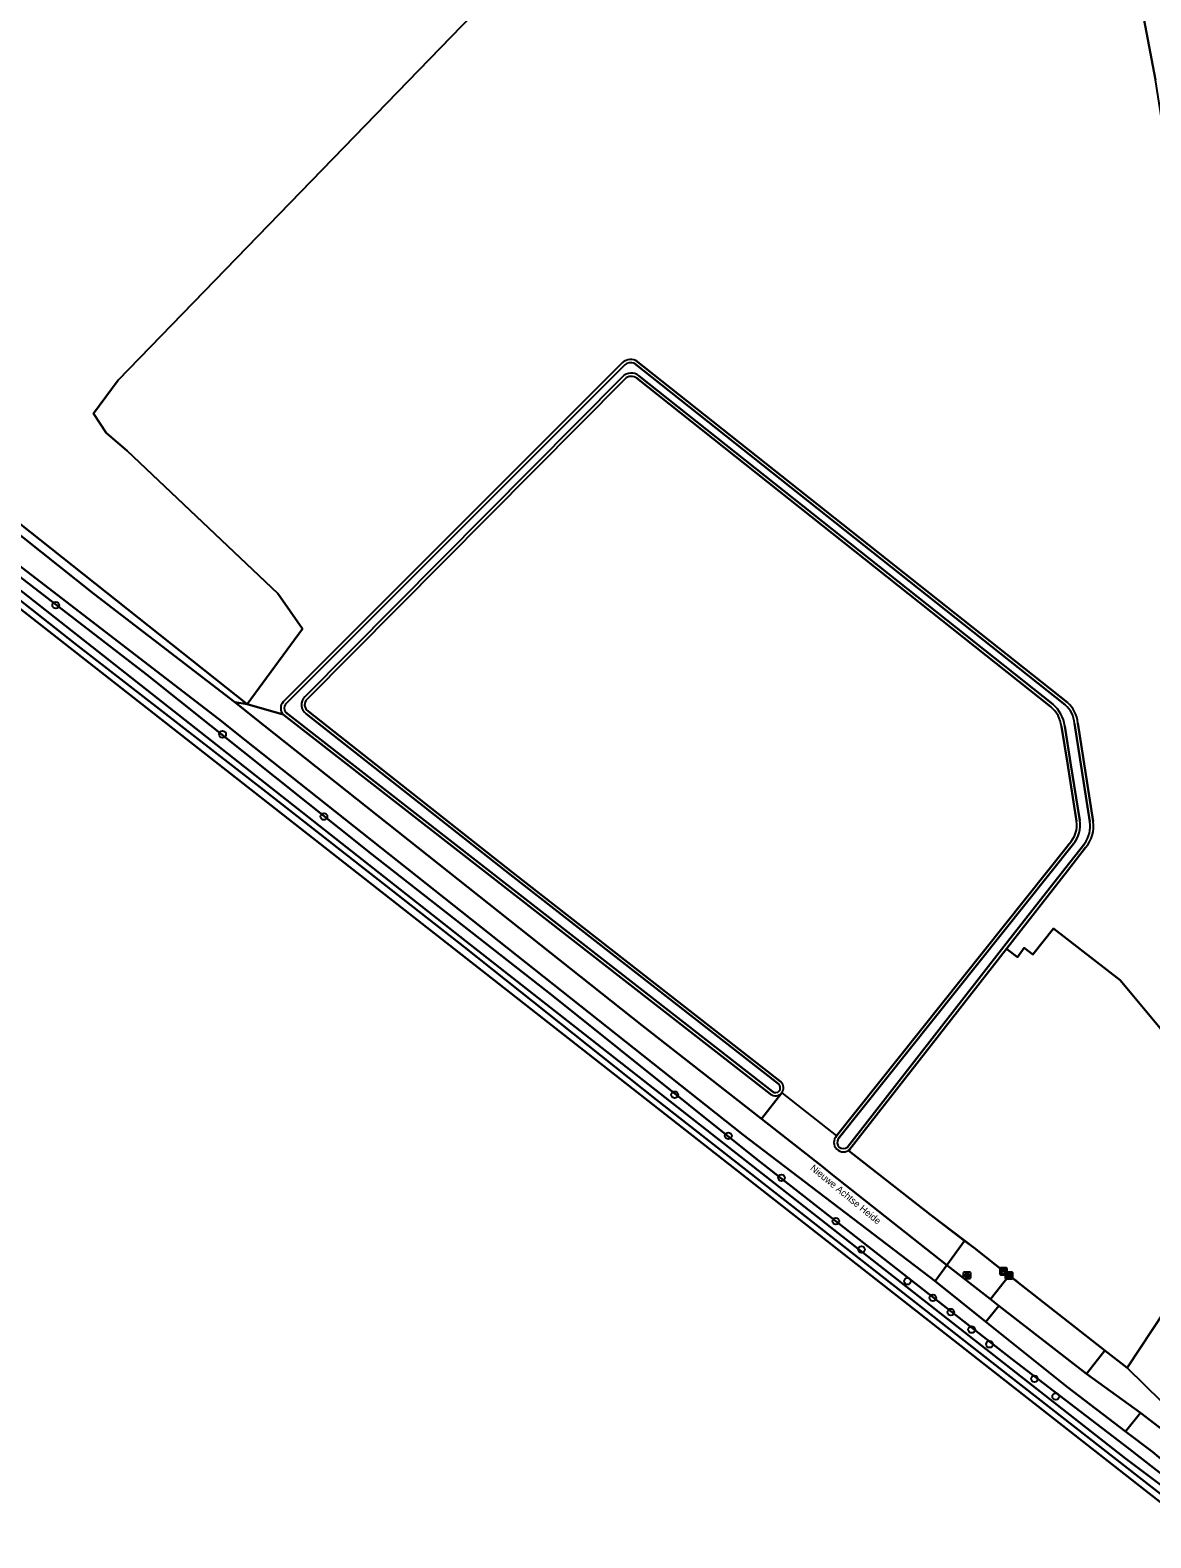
# Model space of a CAD drawing. Extents: x 155209 to 156748, y 385356 to 388487.
# Drawn here: x 155848.9 to 156012.2, y 387555.6 to 387775.3 of the extents above; entities that cross this region are included whole.
import ezdxf

# ---------------------------------------------------------------- set-up
doc = ezdxf.new("R2010")
doc.units = 0
for name, color, linetype in [('IMGEO_Boom', 7, 'Continuous'), ('IMGEO_Bouwland', 7, 'Continuous'), ('IMGEO_Duiker', 7, 'Continuous'), ('IMGEO_Erf', 7, 'Continuous'), ('IMGEO_Grasland_overig', 7, 'Continuous'), ('IMGEO_Groenvoorziening', 7, 'Continuous'), ('IMGEO_Kast', 7, 'Continuous'), ('IMGEO_Loofbos', 7, 'Continuous'), ('IMGEO_Muur', 7, 'Continuous'), ('IMGEO_Oever', 7, 'Continuous'), ('IMGEO_Openbare_ruimte_label', 7, 'Continuous'), ('IMGEO_Rijbaan_lokaal_gesloten', 7, 'Continuous'), ('IMGEO_Rijbaan_lokaal_onverhard', 7, 'Continuous'), ('IMGEO_Rijbaan_lokaal_open', 7, 'Continuous'), ('IMGEO_Rioolput', 7, 'Continuous'), ('IMGEO_Sloot', 7, 'Continuous'), ('IMGEO_Voetpad_open', 7, 'Continuous'), ('IMGEO_Waterloop', 7, 'Continuous')]:
    doc.layers.add(name, color=color, linetype=linetype)

msp = doc.modelspace()

# ---------------------------------------------------------------- linework, layer by layer
at = {"layer": 'IMGEO_Boom'}
for centre in [(155852.58, 387691.54), (155876.9, 387672.71), (155891.66, 387660.72), (155942.77, 387620.19), (155950.59, 387614.19), (155958.34, 387608.09), (155966.26, 387601.76), (155969.99, 387597.64), (155976.7, 387593.01), (155980.4, 387590.59), (155983.01, 387588.52), (155986.05, 387585.96), (155988.65, 387583.82), (155995.21, 387578.79), (155998.3, 387576.22)]:
    msp.add_circle(centre, 0.489, dxfattribs=at)
at = {"layer": 'IMGEO_Bouwland'}
for points in [[(155754.24, 387777.78), (155752.39, 387767.82), (155752.83, 387767.55), (155760.37, 387762.65), (155760.73, 387766.41), (155762.05, 387769.58), (155805.98, 387736.24), (155880.46, 387677.11), (155888.52, 387688.09), (155884.95, 387693.25), (155862.99, 387714.02), (155859.95, 387716.66), (155858.1, 387719.44), (155861.67, 387724.34), (155938.4, 387803.45)], [(156020.19, 387555.62), (156015.97, 387558.92), (156015.9, 387558.97), (155781.09, 387742.94), (155776.56, 387746.49), (155759.31, 387760.01), (155760.37, 387762.65), (155752.83, 387767.55), (155752.39, 387767.82), (155752.06, 387766.1), (155750.62, 387758.37), (155749.73, 387755.64), (155749.25, 387753.94), (155746.67, 387748.61), (155744.31, 387742.42), (155741.32, 387737.37), (155735.98, 387729.41), (155729.29, 387720.91), (155724.45, 387715.25), (155719.03, 387709.53), (155710.76, 387701.68), (155707.05, 387698.08), (155703.22, 387694.35), (155700.2, 387690.91)]]:
    msp.add_lwpolyline(points, dxfattribs=at)
at = {"layer": 'IMGEO_Duiker'}
msp.add_lwpolyline([(155958.37, 387620.45), (155966.36, 387614.2)], dxfattribs=at)
at = {"layer": 'IMGEO_Erf'}
msp.add_lwpolyline([(156013.5, 387629.9), (156007.67, 387636.87), (155998, 387644.4), (155994.98, 387640.64), (155993.71, 387641.58), (155992.72, 387640.24), (155991.14, 387641.47), (155968.32, 387612.24), (155968.13, 387612), (155980.01, 387602.73), (155985.03, 387598.91), (155986.4, 387597.87), (155989.48, 387595.46), (155991.51, 387593.86), (156005.46, 387582.93), (156008.69, 387580.4), (156023.21, 387602.29), (156025.53, 387607.15), (156026.18, 387610.83), (156025.05, 387613.71), (156022.6, 387616.69)], close=True, dxfattribs=at)
at = {"layer": 'IMGEO_Grasland_overig'}
for points in [[(156010.63, 387779.89), (156012.82, 387768.11)], [(155935.5, 387724.48), (155889.21, 387677.82)], [(155997.6, 387676.73), (155937.28, 387724.59)], [(155889.36, 387676.09), (155919.07, 387652.63), (155958.26, 387622.07)], [(156000, 387668.49), (155999.14, 387673.85)], [(156001.35, 387660.08), (156000, 387668.49)], [(155966.36, 387614.2), (156000, 387656.42), (156000.26, 387656.74)], [(155958.37, 387620.45), (155955.41, 387616.68), (155964.39, 387609.63), (155965.55, 387608.69), (155982.42, 387595.34), (155985.03, 387598.91), (155980.01, 387602.73), (155968.13, 387612), (155968.32, 387612.24)], [(156016.26, 387573.02), (156008.69, 387580.4), (156005.46, 387582.93), (156002.78, 387579.5), (156010.68, 387573.81), (156020.3, 387566.41)]]:
    msp.add_lwpolyline(points, dxfattribs=at)
msp.add_lwpolyline([(155805.98, 387736.24), (155762.05, 387769.58), (155760.73, 387766.41), (155760.37, 387762.65), (155761.75, 387762.78), (155763.39, 387767.02), (155776.38, 387757.04), (155816.85, 387726), (155858.15, 387693.18), (155878.67, 387677.4), (155880.46, 387677.11)], close=True, dxfattribs=at)
for centre, radius, start, end in [((155936.46, 387723.49), 1.38, 53.2962, 133.6598), ((155889.95, 387677.01), 1.1, 132.8115, 237.254), ((155994.61, 387673.27), 4.57, 7.3643, 49.1467), ((155997.41, 387659.52), 3.98, 315.771, 8.0723), ((155957.44, 387621.2), 1.19, 320.9755, 46.7373), ((155967.37, 387613.25), 1.39, 136.9935, 312.9481)]:
    msp.add_arc(centre, radius, start, end, dxfattribs=at)
at = {"layer": 'IMGEO_Groenvoorziening'}
for points in [[(155952.77, 387614.37), (155880.15, 387671.9), (155876.29, 387674.98), (155795.66, 387736.94), (155783.72, 387746.22), (155779.18, 387749.74), (155776.56, 387746.49), (155781.09, 387742.94), (155780.81, 387743.63), (155781.49, 387744.6), (155782.63, 387745.58), (155783.17, 387745.53), (155790.21, 387739.91), (155844.98, 387697.49), (155865.76, 387681.47), (155898.69, 387655.19), (155925.06, 387634.57), (155954.59, 387610.92), (155991.79, 387581.76), (156009, 387568.58), (156018.08, 387561.51)], [(156020.96, 387560.91), (156017.92, 387563.49), (156012.41, 387568.14), (156008.49, 387571.12), (156000, 387577.57), (155988.1, 387587.08), (155980.71, 387593), (155952.77, 387614.37)]]:
    msp.add_lwpolyline(points, dxfattribs=at)
at = {"layer": 'IMGEO_Kast'}
for p, q in [((155990.2, 387594.03), (155990.2, 387594.88)), ((155990.2, 387594.88), (155990.2, 387594.03)), ((155990.27, 387594.96), (155991.11, 387594.96)), ((155991.11, 387594.96), (155990.27, 387594.96)), ((155991, 387593.41), (155991, 387594.25)), ((155991, 387594.25), (155991, 387593.41)), ((155991.07, 387594.34), (155991.91, 387594.34)), ((155991.91, 387594.34), (155991.07, 387594.34)), ((155991.2, 387594.89), (155991.2, 387594.04)), ((155991.2, 387594.04), (155991.2, 387594.89)), ((155992, 387594.26), (155992, 387593.42)), ((155992, 387593.42), (155992, 387594.26)), ((155991.12, 387593.96), (155990.28, 387593.96)), ((155990.28, 387593.96), (155991.12, 387593.96)), ((155991.92, 387593.34), (155991.08, 387593.34)), ((155991.08, 387593.34), (155991.92, 387593.34))]:
    msp.add_line(p, q, dxfattribs=at)
for points in [[(155990.39, 387594.75), (155990.99, 387594.75), (155990.99, 387594.66), (155990.39, 387594.66), (155990.39, 387594.75)], [(155990.39, 387594.58), (155990.99, 387594.58), (155990.99, 387594.09), (155990.39, 387594.09), (155990.39, 387594.58)], [(155991.19, 387594.13), (155991.79, 387594.13), (155991.79, 387594.04), (155991.19, 387594.04), (155991.19, 387594.13)], [(155991.19, 387593.95), (155991.79, 387593.95), (155991.79, 387593.47), (155991.19, 387593.47), (155991.19, 387593.95)]]:
    msp.add_lwpolyline(points, dxfattribs=at)
for centre in [(155990.48, 387594.42), (155991.27, 387593.8)]:
    msp.add_circle(centre, 0.0377, dxfattribs=at)
for centre, start, end in [((155990.28, 387594.88), 92.4484, 184.2845), ((155990.28, 387594.88), 92.4484, 184.2845), ((155991.07, 387594.26), 92.4484, 184.2845), ((155991.07, 387594.26), 92.4484, 184.2845), ((155991.12, 387594.88), 2.4484, 94.2845), ((155991.12, 387594.88), 2.4484, 94.2845), ((155991.92, 387594.26), 2.4484, 94.2845), ((155991.92, 387594.26), 2.4484, 94.2845), ((155990.28, 387594.04), 182.4484, 274.2845), ((155990.28, 387594.04), 182.4484, 274.2845), ((155991.07, 387593.42), 182.4484, 274.2845), ((155991.07, 387593.42), 182.4484, 274.2845), ((155991.12, 387594.04), 272.4484, 4.2845), ((155991.12, 387594.04), 272.4484, 4.2845), ((155991.92, 387593.42), 272.4484, 4.2845), ((155991.92, 387593.42), 272.4484, 4.2845)]:
    msp.add_arc(centre, 0.0779, start, end, dxfattribs=at)
at = {"layer": 'IMGEO_Loofbos'}
for points in [[(156014.25, 387759.08), (156012.82, 387768.11), (156010.63, 387779.89), (156004.88, 387808.19), (156001.83, 387817.98), (156000.72, 387825.19), (156000.05, 387831.89), (155999.01, 387836.95), (155996.61, 387838.37), (155989.33, 387835.59), (155950.04, 387812.44), (155938.4, 387803.45), (155861.67, 387724.34), (155858.1, 387719.44), (155859.95, 387716.66), (155862.99, 387714.02), (155884.95, 387693.25), (155888.52, 387688.09), (155880.46, 387677.11), (155885.7, 387675.61)], [(155885.7, 387677.44), (155934.98, 387726.71)], [(155937.1, 387727.2), (156000, 387677.37)], [(155885.7, 387675.61), (155880.46, 387677.11), (155878.67, 387677.4), (155883, 387673.97), (155938.06, 387630.28), (155955.41, 387616.68), (155958.37, 387620.45)], [(155956.73, 387620.29), (155885.7, 387675.61)], [(156001.53, 387674.36), (156003.74, 387660.01)], [(156002.65, 387656.21), (156000, 387652.82), (155991.14, 387641.47), (155992.72, 387640.24), (155993.71, 387641.58), (155994.98, 387640.64), (155998, 387644.4), (156007.67, 387636.87), (156013.5, 387629.9)], [(156023.21, 387602.29), (156008.69, 387580.4), (156016.26, 387573.02)]]:
    msp.add_lwpolyline(points, dxfattribs=at)
for centre, radius, start, end in [((155936.39, 387725.41), 1.92, 68.3536, 137.4506), ((155886.8, 387676.52), 1.43, 140.1849, 219.8151), ((155996.96, 387673.92), 4.6, 5.4947, 48.5021), ((155999.24, 387659.25), 4.57, 318.292, 9.5745), ((155957.47, 387621.22), 1.18, 231.855, 319.6702)]:
    msp.add_arc(centre, radius, start, end, dxfattribs=at)
at = {"layer": 'IMGEO_Muur'}
for points in [[(155992.72, 387640.24), (155993.71, 387641.58), (155994.98, 387640.64), (155998, 387644.4), (156007.67, 387636.87), (156013.5, 387629.9), (156022.6, 387616.69), (156025.05, 387613.71), (156026.18, 387610.83), (156025.53, 387607.15), (156023.21, 387602.29), (156008.69, 387580.4)], [(155980.01, 387602.73), (155986.4, 387597.87)], [(155989.48, 387595.46), (155992.71, 387592.93)], [(156008.69, 387580.4), (155994.6, 387591.45)]]:
    msp.add_lwpolyline(points, dxfattribs=at)
at = {"layer": 'IMGEO_Oever'}
for points in [[(156018.08, 387561.51), (156009, 387568.58), (155991.79, 387581.76), (155954.59, 387610.92), (155925.06, 387634.57), (155898.69, 387655.19), (155865.76, 387681.47), (155844.98, 387697.49), (155790.21, 387739.91), (155783.17, 387745.53), (155782.63, 387745.58), (155781.49, 387744.6), (155780.81, 387743.63), (155781.09, 387742.94)], [(155781.09, 387742.94), (156015.9, 387558.97), (156015.97, 387558.92)], [(155934.98, 387726.71), (155885.7, 387677.44)], [(155886.06, 387677.12), (155935.51, 387726.56)], [(155936.86, 387726.78), (155999.69, 387677)], [(156000, 387677.37), (155937.1, 387727.2)], [(155935.17, 387724.83), (155888.87, 387678.16)], [(155889.21, 387677.82), (155935.5, 387724.48)], [(155937.28, 387724.59), (155997.6, 387676.73)], [(155997.9, 387677.1), (155937.57, 387724.97)], [(155885.7, 387675.61), (155956.73, 387620.29)], [(155957.04, 387620.66), (155886.04, 387675.95)], [(155889.08, 387675.7), (155918.78, 387652.26), (155957.95, 387621.71)], [(155958.26, 387622.07), (155919.07, 387652.63), (155889.36, 387676.09)], [(155999.14, 387673.85), (156000, 387668.49), (156001.35, 387660.08)], [(156001.82, 387660.15), (156000.47, 387668.57), (155999.61, 387673.92)], [(156001.06, 387674.31), (156003.27, 387659.94)], [(156003.74, 387660.01), (156001.53, 387674.36)], [(156000.26, 387656.74), (156000, 387656.42), (155966.36, 387614.2)], [(155966.62, 387613.76), (156000.89, 387656.73)], [(156002.52, 387656.8), (155999.62, 387653.11), (155990.76, 387641.77), (155967.96, 387612.57)], [(155968.32, 387612.24), (155991.14, 387641.47), (156000, 387652.82), (156002.65, 387656.21)]]:
    msp.add_lwpolyline(points, dxfattribs=at)
msp.add_lwpolyline([(155782.52, 387743.29), (155781.68, 387743.99), (155781.84, 387744.62), (155782.25, 387744.9), (155782.59, 387744.7), (155783.27, 387744.19), (155913.04, 387642.03), (156008.48, 387567.2), (156017.02, 387560.75), (156016.28, 387559.89), (155991.72, 387579.09), (155940.14, 387619.46), (155912.17, 387641.68), (155883.3, 387664.26), (155855.38, 387685.95), (155823.51, 387711.04), (155792.13, 387735.84)], close=True, dxfattribs=at)
for centre, radius, start, end in [((155936.39, 387725.41), 1.92, 68.3536, 137.4506), ((155936.39, 387725.42), 1.44, 70.8925, 127.592), ((155936.46, 387723.49), 1.86, 53.012, 133.9389), ((155936.46, 387723.49), 1.38, 53.2962, 133.6598), ((155889.95, 387677.01), 1.57, 133.2167, 236.3183), ((155889.95, 387677.01), 1.1, 132.8115, 237.254), ((155886.8, 387676.52), 1.43, 140.1849, 219.8151), ((155886.8, 387676.52), 0.949, 141.3982, 217.0267), ((155994.61, 387673.27), 4.57, 7.3643, 49.1467), ((155994.6, 387673.26), 5.06, 7.4983, 49.2303), ((155996.96, 387673.93), 4.11, 5.2867, 48.3694), ((155996.96, 387673.92), 4.6, 5.4947, 48.5021), ((155997.41, 387659.52), 3.98, 315.771, 8.0723), ((155997.41, 387659.52), 4.46, 321.2984, 8.1261), ((155999.23, 387659.26), 4.1, 323.2418, 9.5995), ((155999.24, 387659.25), 4.57, 318.292, 9.5745), ((155957.47, 387621.2), 0.695, 231.4798, 46.521), ((155957.44, 387621.2), 1.19, 320.9755, 46.7373), ((155957.47, 387621.22), 1.18, 231.855, 319.6702), ((155967.37, 387613.25), 1.39, 136.9935, 312.9481), ((155967.37, 387613.25), 0.908, 145.8711, 310.8829)]:
    msp.add_arc(centre, radius, start, end, dxfattribs=at)
at = {"layer": 'IMGEO_Rijbaan_lokaal_gesloten'}
for points in [[(155990, 387589.45), (155988.1, 387587.08), (156000, 387577.57), (156008.49, 387571.12), (156010.68, 387573.81), (156002.78, 387579.5)], [(156010.68, 387573.81), (156008.49, 387571.12), (156012.41, 387568.14), (156017.92, 387563.49), (156020.3, 387566.41)]]:
    msp.add_lwpolyline(points, close=True, dxfattribs=at)
at = {"layer": 'IMGEO_Rijbaan_lokaal_onverhard'}
msp.add_lwpolyline([(155938.06, 387630.28), (155883, 387673.97), (155878.67, 387677.4), (155858.15, 387693.18), (155816.85, 387726), (155776.38, 387757.04), (155763.39, 387767.02), (155761.75, 387762.78), (155778.16, 387750.54), (155779.18, 387749.74), (155783.72, 387746.22), (155795.66, 387736.94), (155876.29, 387674.98), (155880.15, 387671.9), (155952.77, 387614.37), (155980.71, 387593), (155982.42, 387595.34), (155965.55, 387608.69), (155964.39, 387609.63), (155955.41, 387616.68)], close=True, dxfattribs=at)
at = {"layer": 'IMGEO_Rijbaan_lokaal_open'}
msp.add_lwpolyline([(155982.42, 387595.34), (155980.71, 387593), (155988.1, 387587.08), (155990, 387589.45), (155988.79, 387590.39)], close=True, dxfattribs=at)
at = {"layer": 'IMGEO_Rioolput'}
for p, q in [((155984.87, 387593.45), (155984.87, 387594.3)), ((155984.95, 387594.37), (155985.8, 387594.37)), ((155985.36, 387594.15), (155985.39, 387594.15)), ((155985.87, 387594.3), (155985.87, 387593.45)), ((155985.8, 387593.37), (155984.95, 387593.37)), ((155985.13, 387593.87), (155985.13, 387593.88)), ((155985.57, 387593.83), (155985.17, 387593.83)), ((155985.18, 387593.92), (155985.57, 387593.92)), ((155985.38, 387593.59), (155985.36, 387593.59)), ((155985.62, 387593.88), (155985.62, 387593.87))]:
    msp.add_line(p, q, dxfattribs=at)
for points in [[(155984.87, 387593.45), (155984.87, 387594.3)], [(155984.95, 387594.37), (155985.8, 387594.37)], [(155985.87, 387594.3), (155985.87, 387593.45)], [(155985.8, 387593.37), (155984.95, 387593.37)]]:
    msp.add_lwpolyline(points, dxfattribs=at)
for centre, radius, start, end in [((155984.95, 387594.3), 0.0765, 91.552, 178.448), ((155984.95, 387594.3), 0.0765, 91.552, 178.448), ((155985.8, 387594.3), 0.0765, 1.552, 88.448), ((155985.8, 387594.3), 0.0765, 1.552, 88.448), ((155984.95, 387593.45), 0.0765, 181.552, 268.448), ((155984.95, 387593.45), 0.0765, 181.552, 268.448), ((155985.17, 387593.88), 0.0403, 85.8775, 175.7526), ((155985.17, 387593.87), 0.0366, 178.938, 274.7102), ((155985.58, 387593.88), 0.0386, 1.7309, 96.639), ((155985.57, 387593.87), 0.043, 264.8664, 352.4533), ((155985.8, 387593.45), 0.0765, 271.552, 358.448), ((155985.8, 387593.45), 0.0765, 271.552, 358.448)]:
    msp.add_arc(centre, radius, start, end, dxfattribs=at)
for centre, major_axis, ratio, start_param, end_param in [((155985.36, 387593.87), (-0.387, 0.002), 0.722429, 4.712389, 7.853982), ((155985.38, 387593.87), (-0.39, 0.002), 0.717154, 1.570796, 4.712389)]:
    msp.add_ellipse(centre, major_axis=major_axis, ratio=ratio, start_param=start_param, end_param=end_param, dxfattribs=at)
at = {"layer": 'IMGEO_Sloot'}
msp.add_lwpolyline([(155783.27, 387744.19), (155782.59, 387744.7), (155782.25, 387744.9), (155781.84, 387744.62), (155781.68, 387743.99), (155782.52, 387743.29), (155792.13, 387735.84), (155823.51, 387711.04), (155855.38, 387685.95), (155883.3, 387664.26), (155912.17, 387641.68), (155940.14, 387619.46), (155991.72, 387579.09), (156016.28, 387559.89), (156017.02, 387560.75), (156008.48, 387567.2), (155913.04, 387642.03)], close=True, dxfattribs=at)
at = {"layer": 'IMGEO_Voetpad_open'}
for points in [[(155989.48, 387595.46), (155986.4, 387597.87), (155985.03, 387598.91), (155982.42, 387595.34), (155988.79, 387590.39), (155991.51, 387593.86)], [(155991.51, 387593.86), (155988.79, 387590.39), (155990, 387589.45), (156002.78, 387579.5), (156005.46, 387582.93)]]:
    msp.add_lwpolyline(points, close=True, dxfattribs=at)
at = {"layer": 'IMGEO_Waterloop'}
for points in [[(155935.51, 387726.56), (155886.06, 387677.12)], [(155999.69, 387677), (155936.86, 387726.78)], [(155888.87, 387678.16), (155935.17, 387724.83)], [(155937.57, 387724.97), (155997.9, 387677.1)], [(155886.04, 387675.95), (155957.04, 387620.66)], [(155957.95, 387621.71), (155918.78, 387652.26), (155889.08, 387675.7)], [(155999.61, 387673.92), (156000.47, 387668.57), (156001.82, 387660.15)], [(156003.27, 387659.94), (156001.06, 387674.31)], [(156000.89, 387656.73), (155966.62, 387613.76)], [(155967.96, 387612.57), (155990.76, 387641.77), (155999.62, 387653.11), (156002.52, 387656.8)]]:
    msp.add_lwpolyline(points, dxfattribs=at)
for centre, radius, start, end in [((155936.39, 387725.42), 1.44, 70.8925, 127.592), ((155936.46, 387723.49), 1.86, 53.012, 133.9389), ((155889.95, 387677.01), 1.57, 133.2167, 236.3183), ((155886.8, 387676.52), 0.949, 141.3982, 217.0267), ((155994.6, 387673.26), 5.06, 7.4983, 49.2303), ((155996.96, 387673.93), 4.11, 5.2867, 48.3694), ((155997.41, 387659.52), 4.46, 321.2984, 8.1261), ((155999.23, 387659.26), 4.1, 323.2418, 9.5995), ((155957.47, 387621.2), 0.695, 231.4798, 46.521), ((155967.37, 387613.25), 0.908, 145.8711, 310.8829)]:
    msp.add_arc(centre, radius, start, end, dxfattribs=at)

# ---------------------------------------------------------------- texts
at = {"layer": 'IMGEO_Openbare_ruimte_label'}
msp.add_text('Nieuwe Achtse Heide', height=1, rotation=320.5614, dxfattribs=at).set_placement((155962.45, 387609.34))

doc.saveas('drawing.dxf')
